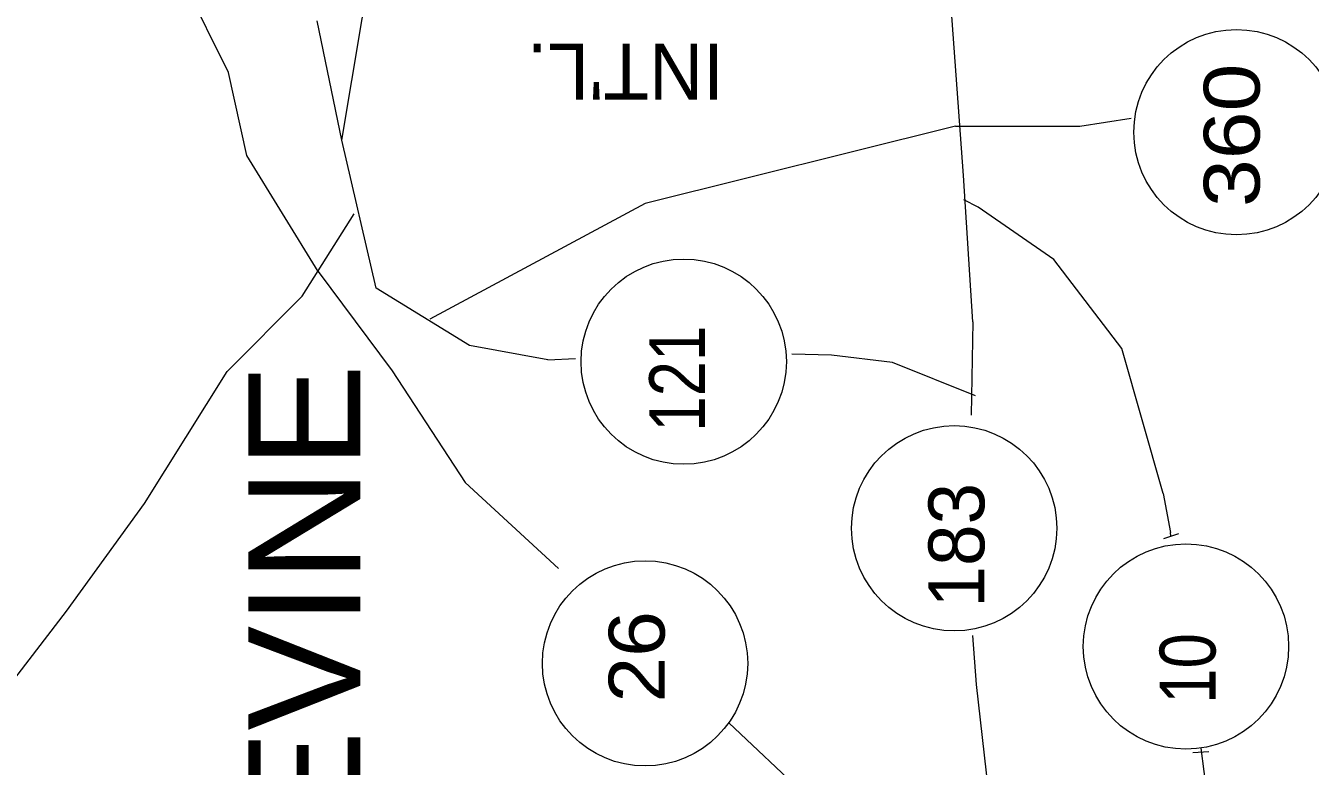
# Model space of a CAD drawing. Extents: x 2363323 to 2367082, y 6956018 to 6980837.
# Drawn here: x 2365875.6 to 2365992.8, y 6956912.2 to 6956979.7 of the extents above; entities that cross this region are included whole.
import ezdxf

# ---------------------------------------------------------------- set-up
doc = ezdxf.new("R2010")
doc.units = 0
doc.header["$LTSCALE"] = 4.1
doc.layers.add('62', color=7, linetype='Continuous', lineweight=13)
doc.layers.add('63', color=7, linetype='Continuous', lineweight=13)

msp = doc.modelspace()

# ---------------------------------------------------------------- linework, layer by layer
at = {"layer": '62'}
for p, q in [((2365904.449, 6956969.294), (2365902.177, 6956980.188)), ((2365971.754, 6956970.579), (2365976.433, 6956971.32)), ((2365960.413, 6956970.578), (2365971.754, 6956970.579)), ((2365962.484, 6956963.174), (2365961.179, 6956963.85)), ((2365900.828, 6956955.074), (2365905.551, 6956962.588)), ((2365961.987, 6956952.734), (2365961.83, 6956944.206)), ((2365923.239, 6956949.246), (2365925.761, 6956949.381)), ((2365949.115, 6956949.696), (2365945.469, 6956949.764)), ((2365915.678, 6956938.064), (2365924.207, 6956930.23)), ((2365979.357, 6956937.05), (2365980.011, 6956933.493)), ((2365979.425, 6956932.953), (2365980.775, 6956933.404)), ((2365980.057, 6956933.156), (2365980.011, 6956933.493)), ((2365962.325, 6956919.633), (2365961.987, 6956924.11)), ((2365949.047, 6956907.369), (2365939.732, 6956916.123)), ((2365983.587, 6956907.706), (2365982.824, 6956913.828)), ((2365982.057, 6956913.446), (2365983.519, 6956913.536))]:
    msp.add_line(p, q, dxfattribs=at)
for points in [[(2365961.987, 6956952.734), (2365961.155, 6956966.076), (2365959.447, 6956989.41), (2365960.391, 6957010.812), (2365961.11, 6957025.054), (2365961.314, 6957043.08), (2365958.837, 6957053.409), (2365951.681, 6957065.288), (2365944.952, 6957078.543), (2365943.803, 6957082.548)], [(2365902.267, 6956957.324), (2365895.787, 6956967.9), (2365894.099, 6956975.458), (2365886.134, 6956991.572)], [(2365907.555, 6956955.795), (2365904.449, 6956969.294), (2365907.194, 6956985.834)], [(2365960.413, 6956970.578), (2365932.106, 6956963.534), (2365912.459, 6956952.981)], [(2365979.357, 6956937.05), (2365975.579, 6956950.281), (2365969.391, 6956958.405), (2365962.484, 6956963.174)], [(2365902.267, 6956957.324), (2365909.039, 6956948.256), (2365915.678, 6956938.064)], [(2365824.322, 6956696.614), (2365819.391, 6956707.214), (2365817.547, 6956721.502), (2365824.929, 6956737.592), (2365825.873, 6956748.528), (2365832.872, 6956762.142), (2365837.575, 6956771.524), (2365840.589, 6956779.605), (2365842.749, 6956790.966), (2365843.625, 6956800.191), (2365844.075, 6956812.344), (2365843.535, 6956826.564), (2365845.831, 6956844.68), (2365846.641, 6956856.47), (2365848.238, 6956869.904), (2365854.813, 6956884.734), (2365861.403, 6956898.816), (2365868.063, 6956911.69), (2365879.313, 6956926.316), (2365886.449, 6956936.15), (2365893.964, 6956948.19), (2365900.828, 6956955.074)], [(2365923.239, 6956949.246), (2365916.081, 6956950.574), (2365907.555, 6956955.795)], [(2365962.235, 6956945.984), (2365954.653, 6956949.021), (2365949.115, 6956949.696)], [(2365966.667, 6956883.608), (2365964.305, 6956902.17), (2365962.325, 6956919.633)]]:
    msp.add_lwpolyline(points, dxfattribs=at)
for centre in [(2365986.039, 6956970.027), (2365935.622, 6956949.091), (2365960.29, 6956933.89), (2365981.432, 6956923.105), (2365932.096, 6956921.564)]:
    msp.add_circle(centre, 9.364, dxfattribs=at)
at = {"layer": '63'}
for p, q in [((2365904.449, 6956969.294), (2365902.177, 6956980.188)), ((2365971.754, 6956970.579), (2365976.433, 6956971.32)), ((2365960.413, 6956970.578), (2365971.754, 6956970.579)), ((2365962.484, 6956963.174), (2365961.179, 6956963.85)), ((2365900.828, 6956955.074), (2365905.551, 6956962.588)), ((2365961.987, 6956952.734), (2365961.83, 6956944.206)), ((2365923.239, 6956949.246), (2365925.761, 6956949.381)), ((2365949.115, 6956949.696), (2365945.469, 6956949.764)), ((2365915.678, 6956938.064), (2365924.207, 6956930.23)), ((2365979.357, 6956937.05), (2365980.011, 6956933.493)), ((2365979.425, 6956932.953), (2365980.775, 6956933.404)), ((2365980.057, 6956933.156), (2365980.011, 6956933.493)), ((2365962.325, 6956919.633), (2365961.987, 6956924.11)), ((2365949.047, 6956907.369), (2365939.732, 6956916.123)), ((2365983.587, 6956907.706), (2365982.824, 6956913.828)), ((2365982.057, 6956913.446), (2365983.519, 6956913.536))]:
    msp.add_line(p, q, dxfattribs=at)
for points in [[(2365961.987, 6956952.734), (2365961.155, 6956966.076), (2365959.447, 6956989.41), (2365960.391, 6957010.812), (2365961.11, 6957025.054), (2365961.314, 6957043.08), (2365958.837, 6957053.409), (2365951.681, 6957065.288), (2365944.952, 6957078.543), (2365943.803, 6957082.548)], [(2365902.267, 6956957.324), (2365895.787, 6956967.9), (2365894.099, 6956975.458), (2365886.134, 6956991.572)], [(2365907.555, 6956955.795), (2365904.449, 6956969.294), (2365907.194, 6956985.834)], [(2365960.413, 6956970.578), (2365932.106, 6956963.534), (2365912.459, 6956952.981)], [(2365979.357, 6956937.05), (2365975.579, 6956950.281), (2365969.391, 6956958.405), (2365962.484, 6956963.174)], [(2365902.267, 6956957.324), (2365909.039, 6956948.256), (2365915.678, 6956938.064)], [(2365824.322, 6956696.614), (2365819.391, 6956707.214), (2365817.547, 6956721.502), (2365824.929, 6956737.592), (2365825.873, 6956748.528), (2365832.872, 6956762.142), (2365837.575, 6956771.524), (2365840.589, 6956779.605), (2365842.749, 6956790.966), (2365843.625, 6956800.191), (2365844.075, 6956812.344), (2365843.535, 6956826.564), (2365845.831, 6956844.68), (2365846.641, 6956856.47), (2365848.238, 6956869.904), (2365854.813, 6956884.734), (2365861.403, 6956898.816), (2365868.063, 6956911.69), (2365879.313, 6956926.316), (2365886.449, 6956936.15), (2365893.964, 6956948.19), (2365900.828, 6956955.074)], [(2365923.239, 6956949.246), (2365916.081, 6956950.574), (2365907.555, 6956955.795)], [(2365962.235, 6956945.984), (2365954.653, 6956949.021), (2365949.115, 6956949.696)], [(2365966.667, 6956883.608), (2365964.305, 6956902.17), (2365962.325, 6956919.633)]]:
    msp.add_lwpolyline(points, dxfattribs=at)
for centre in [(2365986.039, 6956970.027), (2365935.622, 6956949.091), (2365960.29, 6956933.89), (2365981.432, 6956923.105), (2365932.096, 6956921.564)]:
    msp.add_circle(centre, 9.364, dxfattribs=at)

# ---------------------------------------------------------------- texts
at = {"layer": '62'}
for s, rotation, p in [("INT'L.", 180, (2365939.282, 6956978.097)), ('183', 90, (2365963.044, 6956926.654))]:
    msp.add_text(s, height=5.099, rotation=rotation, dxfattribs=at).set_placement(p)
for s, height, width, p in [('360', 5.099, 1.15, (2365988.158, 6956963.199)), ('121', 5.099, 0.85, (2365937.572, 6956942.701)), ('GRAPEVINE', 10.21, 1.05, (2365906.114, 6956865.245)), ('26', 5.099, 1.1, (2365933.881, 6956917.991)), ('10', 5.099, 0.85, (2365984.128, 6956917.879))]:
    msp.add_text(s, height=height, rotation=90, dxfattribs=dict(at, width=width)).set_placement(p)
at = {"layer": '63'}
for s, rotation, p in [("INT'L.", 180, (2365939.282, 6956978.097)), ('183', 90, (2365963.044, 6956926.654))]:
    msp.add_text(s, height=5.099, rotation=rotation, dxfattribs=at).set_placement(p)
for s, height, width, p in [('360', 5.099, 1.15, (2365988.158, 6956963.199)), ('121', 5.099, 0.85, (2365937.572, 6956942.701)), ('GRAPEVINE', 10.21, 1.05, (2365906.114, 6956865.245)), ('26', 5.099, 1.1, (2365933.881, 6956917.991)), ('10', 5.099, 0.85, (2365984.128, 6956917.879))]:
    msp.add_text(s, height=height, rotation=90, dxfattribs=dict(at, width=width)).set_placement(p)

doc.saveas('drawing.dxf')
